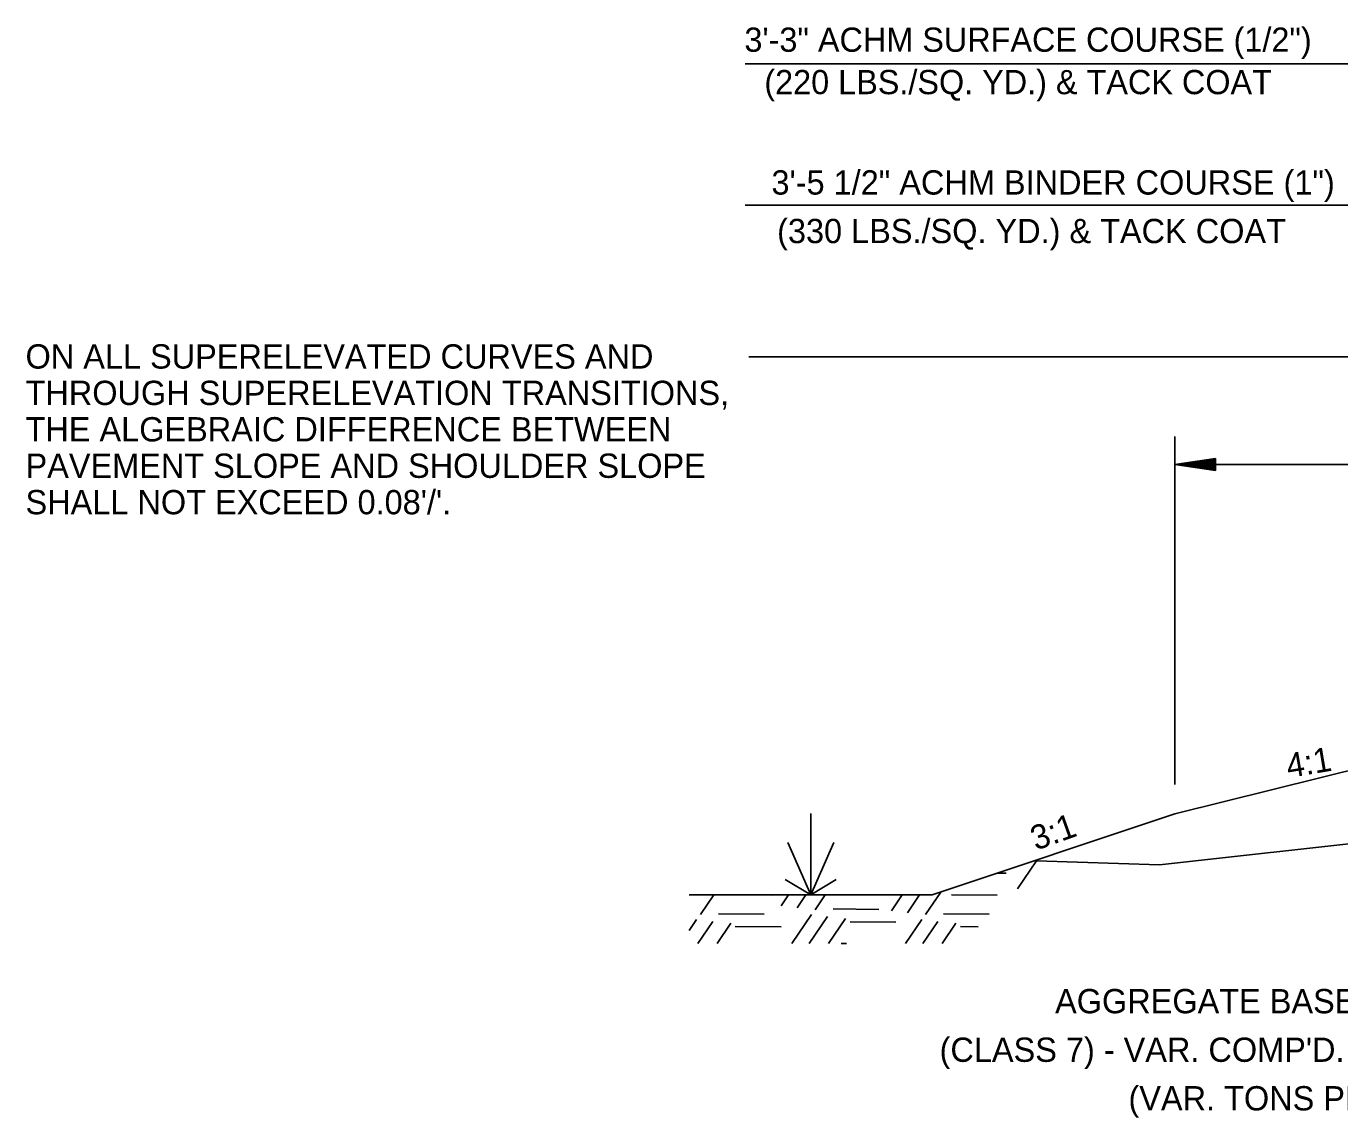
# Model space of a CAD drawing. Extents: x 2478 to 3210, y 439 to 841.
# Drawn here: x 2924.5 to 2989.4, y 766.9 to 820.8 of the extents above; entities that cross this region are included whole.
import ezdxf

# ---------------------------------------------------------------- set-up
doc = ezdxf.new("R2010")
doc.units = 0
for name, color, linetype in [('R_Annotation', 7, 'Continuous'), ('R_Dimension', 7, 'Continuous'), ('R_Draft', 7, 'Continuous'), ('R_Exist Surface', 7, 'Continuous')]:
    doc.layers.add(name, color=color, linetype=linetype)

msp = doc.modelspace()

# ---------------------------------------------------------------- linework, layer by layer
at = {"layer": 'R_Annotation'}
for p, q in [((3001.233, 786.863), (2981.233, 781.863)), ((2981.233, 781.863), (2969.233, 777.863)), ((2969.233, 777.863), (2957.233, 777.863))]:
    msp.add_line(p, q, dxfattribs=at)
at = {"layer": 'R_Dimension'}
for p, q in [((3011.233, 818.934), (2959.991, 818.934)), ((3011.233, 811.949), (2959.991, 811.949)), ((2960.169, 804.453), (2994.516, 804.453)), ((2981.233, 783.318), (2981.233, 800.517)), ((2983.233, 799.43), (2981.233, 799.13)), ((2981.233, 799.13), (3009.233, 799.13)), ((2983.233, 798.83), (2981.233, 799.13)), ((2983.233, 799.38), (2981.567, 799.13)), ((2983.233, 798.88), (2981.567, 799.13)), ((2983.233, 799.329), (2981.911, 799.13)), ((2983.233, 798.931), (2981.911, 799.13)), ((2983.233, 799.279), (2982.244, 799.13)), ((2983.233, 798.981), (2982.244, 799.13)), ((2983.233, 799.228), (2982.583, 799.13)), ((2983.233, 799.033), (2982.583, 799.13)), ((2983.233, 799.177), (2982.917, 799.13)), ((2983.233, 799.083), (2982.917, 799.13)), ((2983.233, 798.83), (2983.233, 799.43)), ((2973.461, 778.159), (2974.394, 779.542)), ((2972.443, 778.933), (2972.892, 778.93)), ((2957.782, 776.889), (2958.439, 777.863)), ((2960.176, 777.863), (2961.323, 777.854)), ((2961.768, 777.316), (2962.138, 777.863)), ((2962.565, 777.223), (2962.997, 777.863)), ((2963.455, 777.13), (2963.95, 777.863)), ((2967.219, 777.075), (2967.751, 777.863)), ((2968.016, 776.982), (2968.611, 777.863)), ((2968.906, 776.889), (2969.659, 778.005)), ((2970.185, 777.872), (2972.447, 777.854)), ((2964.345, 777.167), (2966.607, 777.149)), ((2957.233, 776.11), (2957.597, 776.648)), ((2957.654, 775.459), (2958.394, 776.555)), ((2958.607, 775.459), (2959.284, 776.463)), ((2958.672, 776.926), (2960.934, 776.908)), ((2962.305, 775.459), (2963.27, 776.889)), ((2963.165, 775.459), (2964.067, 776.796)), ((2964.117, 775.459), (2964.957, 776.704)), ((2965.18, 776.537), (2967.441, 776.518)), ((2967.918, 775.459), (2968.721, 776.648)), ((2968.778, 775.459), (2969.518, 776.555)), ((2969.731, 775.459), (2970.408, 776.463)), ((2969.796, 776.926), (2972.058, 776.908)), ((2959.506, 776.296), (2961.768, 776.277)), ((2970.63, 776.296), (2971.516, 776.288)), ((2964.735, 775.461), (2965.005, 775.459))]:
    msp.add_line(p, q, dxfattribs=at)
at = {"layer": 'R_Draft'}
for q in [(2963.233, 781.881), (2962.095, 780.449), (2964.372, 780.449), (2961.975, 778.621), (2964.492, 778.621)]:
    msp.add_line((2963.233, 777.863), q, dxfattribs=at)
at = {"layer": 'R_Exist Surface'}
msp.add_lwpolyline([(2974.394, 779.542), (2980.464, 779.356), (2991.6, 780.578), (3008.322, 785.91), (3009.233, 786.036), (3031.233, 785.919), (3053.233, 785.156), (3055.82, 784.789), (3076.957, 782.83), (3083.428, 781.714), (3088.64, 782.82)], dxfattribs=at)

# ---------------------------------------------------------------- texts
at = {"layer": 'R_Annotation'}
for s, height, p in [('3\'-3" ACHM SURFACE COURSE (1/2")', 1.197, (2959.957, 819.524)), ('(220 LBS./SQ. YD.) & TACK COAT', 1.197, (2960.942, 817.429)), ('3\'-5 1/2" ACHM BINDER COURSE (1")', 1.2, (2961.294, 812.468)), ('(330 LBS./SQ. YD.) & TACK COAT', 1.2, (2961.573, 810.068)), ('ON ALL SUPERELEVATED CURVES AND', 1.2, (2924.429, 803.87)), ('THROUGH SUPERELEVATION TRANSITIONS,', 1.2, (2924.429, 802.07)), ('THE ALGEBRAIC DIFFERENCE BETWEEN', 1.2, (2924.429, 800.27)), ('PAVEMENT SLOPE AND SHOULDER SLOPE', 1.2, (2924.429, 798.47)), ("SHALL NOT EXCEED 0.08'/'.", 1.2, (2924.429, 796.67)), ('AGGREGATE BASE COURSE', 1.2, (2975.31, 772.013)), ("(CLASS 7) - VAR. COMP'D. DEPTH", 1.2, (2969.603, 769.613)), ('(VAR. TONS PER STA.)', 1.2, (2978.938, 767.213))]:
    msp.add_text(s, height=height, dxfattribs=at).set_placement(p)
for s, rotation, p in [('4:1', 9.57537, (2986.842, 783.637)), ('3:1', 19.62862, (2974.363, 780.045))]:
    msp.add_text(s, height=1.2, rotation=rotation, dxfattribs=at).set_placement(p)

doc.saveas('drawing.dxf')
